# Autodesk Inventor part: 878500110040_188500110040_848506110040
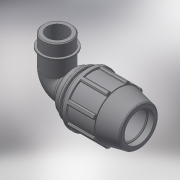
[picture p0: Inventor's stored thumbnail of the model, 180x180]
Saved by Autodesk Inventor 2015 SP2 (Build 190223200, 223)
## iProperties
Created: 2017-02
Part Number: 878500110040_188500110040_848506110040
Material: Generic
Description: PLASSON 90° ELBOW MALE ADAPTOR 110-4"
Document SubType Name: Modeling
Designer: KIM
Mass: 1366.09 g
Surface Area: 1816.46 cm^2
Volume: 1366.09 cm^3
Density: 1 g/cm^3
Appearance: Default
Author: KIM
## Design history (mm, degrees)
derived "87850.ipt"
feature "Solid1::87850.ipt"
tag "TaggingFeature1"
body "Solid1"
other parameters: "d4" = 23, "d5" = 69, "d7" = 181, "d9" = 39.42857, "d11" = 9.2, "d13" = 120 deg, "d14" = 132, "d15" = 12 deg, "d16" = 157.47, "d18" = 5.5, "d19" = 35 deg, "d20" = 17.5 deg, "d21" = 168.33, "d23" = 0, "d25" = 360 deg, "d27" = 3.62, "d33" = 2.2, "d42" = 102.12, "d43" = 5.43, "d46" = 3.3, "d51" = 276, "d68" = 18.4, "d73" = 113.03, "d74" = 42, "d75" = 129.9845, "d76" = 79.121, "d77" = 46.2, "d79" = 45.212, "d80" = 3.3909, "d83" = 0, "d84" = 0, "d91" = 135.75, "d93" = 196, "d94" = 113.03, "d95" = 79.121, "d96" = 18.4, "d97" = 50 deg, "d98" = 4.6, "d99" = 152.7459, "d100" = 4.6, "d101" = 4.6, "d102" = 12.06667, "d103" = 0, "E_" = 181, "A_" = 276, "l_" = 196, "l_2" = 42, "G_" = 113.03
